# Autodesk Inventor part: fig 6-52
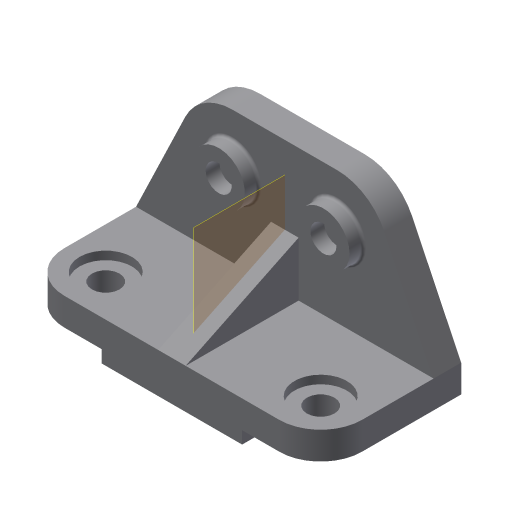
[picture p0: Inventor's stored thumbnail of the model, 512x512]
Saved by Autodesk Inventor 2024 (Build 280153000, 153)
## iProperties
Shininess: 77.0
Length Units: 11269
Angle Units: 11279
Time Units: 11290
Mass Units: 11283
Length Display Precision: 3
Angle Display Precision: 2
Created: 2001-12
Part Number: fig 6-52
Document SubType Name: Modeling
Designer: Renu Muthoo
Density: 1 g/cm^3
Material: Generic
Appearance: Default
Density: 0.0
Volumn: 0.0
Area: 0.0
PropertySet Name: Model Information
Control State: 0
Master: False
Checked Out: False
Author: Renu Muthoo
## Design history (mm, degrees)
sketch "Sketch2"
  geometry: L1 (-67.219, 19.116)-(148.781, 19.116); L2 (148.781, 19.116)-(148.781, -0.884); L3 (-67.219, -0.884)-(-67.219, 19.116); L4 (-10.219, -0.884)-(-10.219, -9.884); L5 (-10.219, -9.884)-(91.781, -9.884); L6 (91.781, -9.884)-(91.781, -0.884); L7 (148.781, -0.884)-(91.781, -0.884); L8 (-10.219, -0.884)-(-67.219, -0.884)
  constraints: 16 end point, 5 parallel, 4 perpendicular, 2 equal length, 1 horizontal
  dimensions: "d0" = 102 distance of L4.end L5.end; "d1" = 57 distance of L4.start L3.start; "d2" = 29 distance between parallel lines of L1 L5; "d3" = 20 distance of L1.end L2.end
extrude "Extrusion1" new body sketch "Sketch2" distance "d4" = 102; taper "d5" = 0 deg
sketch "Sketch3"
  geometry: L1 (67.219, -19.116)-(-148.781, -19.116) reference; L2 (67.219, -19.116)-(31.475, -93.564); L3 (-2.781, -115.116)-(-78.781, -115.116); L4 (-113.038, -93.564)-(-148.781, -19.116); A1 r 38 centre (-2.781, -77.116) between (-2.781, -115.116) and (31.475, -93.564); A2 r 38 centre (-78.781, -77.116) between (-113.038, -93.564) and (-78.781, -115.116)
  constraints: 6 end point, 4 point on circle, 4 tangent, 2 centre point, 1 equal length, 1 equal radius, 1 parallel
  dimensions: "d6" = 96 distance between parallel lines of L3 L1; "d7" = 38 radius of A1; "d8" = 76 distance of A2.centre A1.centre
extrude "Extrusion2" join sketch "Sketch3" distance "d9" = 20; taper "d10" = 0 deg
fillet "Fillet1" dims "d11" = 30
workplane "Work Plane1"
sketch "Sketch5"
  geometry: A1 r 30 centre (-30, 0) between (-30, -30) and (0, 0) reference; 1 further point
  constraints: 1 coincident
hole "Hole1" sketch "Sketch5" diameter "d16" = 20; stored, may be unused: countersink angle "d20" = 82 deg, drill point angle "d22" = 118 deg; dims "d17" = 6, "d18" = 38, "d19" = 6, "d21" = 8
sketch "Sketch6"
  geometry: C1 r 19 at (-2.781, 77.116); C2 r 9.5 at (-2.781, 77.116); A1 r 38 centre (-2.781, 77.116) between (31.475, 93.564) and (-2.781, 115.116) reference
  constraints: 2 centre point, 2 coincident
  dimensions: "d23" = 38 diameter of C1; "d24" = 19 diameter of C2
extrude "Extrusion3" join sketch "Sketch6" distance "d25" = 10; taper "d26" = 0 deg
sketch "Sketch7"
  geometry: L1 (0, -82)-(-39.557, 0); L2 (0, -82)-(20, -82) reference; L3 (29, 22.405)-(29, -82); L4 (29, -82)-(0, -82); L5 (0, -82)-(0, 0); L6 (0, 0)-(-90.034, 0); L7 (-90.034, 0)-(-90.034, 22.405); L8 (-90.034, 22.405)-(29, 22.405); L9 (0, 0)-(-74.447, 0) reference
  constraints: 14 end point, 1 collinear, 1 point on line
feature "Rib3" sketch "Sketch7" dims "d35" = 10, "d36" = 20
fillet "Fillet3" dims "d37" = 2
mirror "Mirror4"
body "Solid1"
node "Sketch1"
other parameters: "d12" = -108
